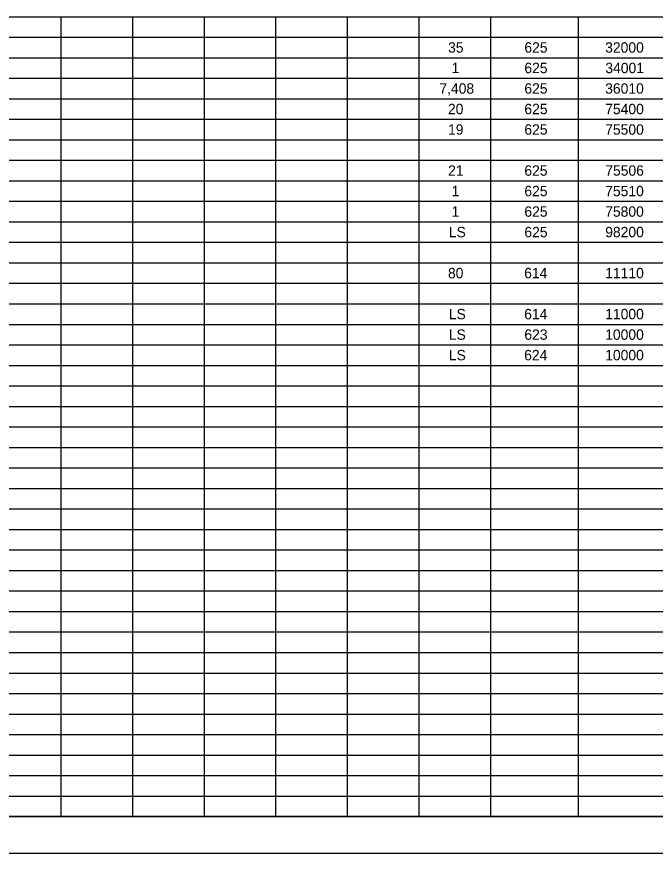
# Model space of a CAD drawing. Extents: x 0 to 34, y 0 to 22.
# Drawn here: x 8.71 to 17.43, y 0 to 11.42 of the extents above; entities that cross this region are included whole.
import ezdxf

# ---------------------------------------------------------------- set-up
doc = ezdxf.new("R2010")
doc.units = 0
for name, color, linetype in [('Default', 7, 'Continuous'), ('SH_Border', 7, 'Continuous'), ('SH_Cut_Line', 7, 'Continuous')]:
    doc.layers.add(name, color=color, linetype=linetype)

msp = doc.modelspace()

# ---------------------------------------------------------------- linework, layer by layer
at = {"layer": 'Default'}
for p, q in [((8.339, 11.42), (13.224, 11.42)), ((9.316, 11.42), (9.316, 10.3)), ((10.293, 11.42), (10.293, 10.3)), ((11.27, 11.42), (11.27, 10.3)), ((12.247, 11.42), (12.247, 10.3)), ((13.224, 11.42), (31.083, 11.42)), ((13.224, 11.42), (13.224, 10.3)), ((14.201, 11.42), (14.201, 10.3)), ((15.178, 11.42), (15.178, 10.3)), ((16.378, 11.42), (16.378, 10.3)), ((8.339, 11.14), (13.224, 11.14)), ((13.224, 11.14), (31.083, 11.14)), ((8.339, 10.86), (13.224, 10.86)), ((13.224, 10.86), (31.083, 10.86)), ((8.339, 10.58), (13.224, 10.58)), ((13.224, 10.58), (31.083, 10.58)), ((8.339, 10.3), (13.224, 10.3)), ((9.316, 10.3), (9.316, 10.02)), ((10.293, 10.3), (10.293, 10.02)), ((11.27, 10.3), (11.27, 10.02)), ((12.247, 10.3), (12.247, 10.02)), ((13.224, 10.3), (31.083, 10.3)), ((13.224, 10.3), (13.224, 10.02)), ((14.201, 10.3), (14.201, 10.02)), ((15.178, 10.3), (15.178, 10.02)), ((16.378, 10.3), (16.378, 10.02)), ((8.339, 10.02), (13.224, 10.02)), ((9.316, 10.02), (9.316, 9.741)), ((10.293, 10.02), (10.293, 9.741)), ((11.27, 10.02), (11.27, 9.741)), ((12.247, 10.02), (12.247, 9.741)), ((13.224, 10.02), (31.083, 10.02)), ((13.224, 10.02), (13.224, 9.741)), ((14.201, 10.02), (14.201, 9.741)), ((15.178, 10.02), (15.178, 9.741)), ((16.378, 10.02), (16.378, 9.741)), ((8.339, 9.741), (13.224, 9.741)), ((9.316, 9.741), (9.316, 8.901)), ((10.293, 9.741), (10.293, 8.901)), ((11.27, 9.741), (11.27, 8.901)), ((12.247, 9.741), (12.247, 8.901)), ((13.224, 9.741), (31.083, 9.741)), ((13.224, 9.741), (13.224, 8.901)), ((14.201, 9.741), (14.201, 8.901)), ((15.178, 9.741), (15.178, 8.901)), ((16.378, 9.741), (16.378, 8.901)), ((8.339, 9.461), (13.224, 9.461)), ((13.224, 9.461), (31.083, 9.461)), ((8.339, 9.181), (13.224, 9.181)), ((13.224, 9.181), (31.083, 9.181)), ((8.339, 8.901), (13.224, 8.901)), ((9.316, 8.901), (9.316, 8.341)), ((10.293, 8.901), (10.293, 8.341)), ((11.27, 8.901), (11.27, 8.341)), ((12.247, 8.901), (12.247, 8.341)), ((13.224, 8.901), (31.083, 8.901)), ((13.224, 8.901), (13.224, 8.341)), ((14.201, 8.901), (14.201, 8.341)), ((15.178, 8.901), (15.178, 8.341)), ((16.378, 8.901), (16.378, 8.341)), ((8.339, 8.621), (13.224, 8.621)), ((13.224, 8.621), (31.083, 8.621)), ((8.339, 8.341), (13.224, 8.341)), ((9.316, 8.341), (9.316, 7.501)), ((10.293, 8.341), (10.293, 7.501)), ((11.27, 8.341), (11.27, 7.501)), ((12.247, 8.341), (12.247, 7.501)), ((13.224, 8.341), (31.083, 8.341)), ((13.224, 8.341), (13.224, 7.501)), ((14.201, 8.341), (14.201, 7.501)), ((15.178, 8.341), (15.178, 7.501)), ((16.378, 8.341), (16.378, 7.501)), ((8.339, 8.061), (13.224, 8.061)), ((13.224, 8.061), (31.083, 8.061)), ((8.339, 7.781), (13.224, 7.781)), ((13.224, 7.781), (31.083, 7.781)), ((8.339, 7.501), (13.224, 7.501)), ((9.316, 7.501), (9.316, 6.941)), ((10.293, 7.501), (10.293, 6.941)), ((11.27, 7.501), (11.27, 6.941)), ((12.247, 7.501), (12.247, 6.941)), ((13.224, 7.501), (31.083, 7.501)), ((13.224, 7.501), (13.224, 6.941)), ((14.201, 7.501), (14.201, 6.941)), ((15.178, 7.501), (15.178, 6.941)), ((16.378, 7.501), (16.378, 6.941)), ((8.339, 7.221), (13.224, 7.221)), ((13.224, 7.221), (31.083, 7.221)), ((8.339, 6.941), (13.224, 6.941)), ((9.316, 6.941), (9.316, 6.101)), ((10.293, 6.941), (10.293, 6.101)), ((11.27, 6.941), (11.27, 6.101)), ((12.247, 6.941), (12.247, 6.101)), ((13.224, 6.941), (31.083, 6.941)), ((13.224, 6.941), (13.224, 6.101)), ((14.201, 6.941), (14.201, 6.101)), ((15.178, 6.941), (15.178, 6.101)), ((16.378, 6.941), (16.378, 6.101)), ((8.339, 6.661), (13.224, 6.661)), ((13.224, 6.661), (31.083, 6.661)), ((8.339, 6.381), (13.224, 6.381)), ((13.224, 6.381), (31.083, 6.381)), ((8.339, 6.101), (13.224, 6.101)), ((9.316, 6.101), (9.316, 4.981)), ((10.293, 6.101), (10.293, 4.981)), ((11.27, 6.101), (11.27, 4.981)), ((12.247, 6.101), (12.247, 4.981)), ((13.224, 6.101), (31.083, 6.101)), ((13.224, 6.101), (13.224, 4.981)), ((14.201, 6.101), (14.201, 4.981)), ((15.178, 6.101), (15.178, 4.981)), ((16.378, 6.101), (16.378, 4.981)), ((8.339, 5.821), (13.224, 5.821)), ((13.224, 5.821), (31.083, 5.821)), ((8.339, 5.541), (13.224, 5.541)), ((13.224, 5.541), (31.083, 5.541)), ((8.339, 5.261), (13.224, 5.261)), ((13.224, 5.261), (31.083, 5.261)), ((8.339, 4.981), (13.224, 4.981)), ((9.316, 4.981), (9.316, 4.701)), ((10.293, 4.981), (10.293, 4.701)), ((11.27, 4.981), (11.27, 4.701)), ((12.247, 4.981), (12.247, 4.701)), ((13.224, 4.981), (31.083, 4.981)), ((13.224, 4.981), (13.224, 4.701)), ((14.201, 4.981), (14.201, 4.701)), ((15.178, 4.981), (15.178, 4.701)), ((16.378, 4.981), (16.378, 4.701)), ((8.339, 4.701), (13.224, 4.701)), ((9.316, 4.701), (9.316, 3.581)), ((10.293, 4.701), (10.293, 3.581)), ((11.27, 4.701), (11.27, 3.581)), ((12.247, 4.701), (12.247, 3.581)), ((13.224, 4.701), (31.083, 4.701)), ((13.224, 4.701), (13.224, 3.581)), ((14.201, 4.701), (14.201, 3.581)), ((15.178, 4.701), (15.178, 3.581)), ((16.378, 4.701), (16.378, 3.581)), ((8.339, 4.421), (13.224, 4.421)), ((13.224, 4.421), (31.083, 4.421)), ((8.339, 4.141), (13.224, 4.141)), ((13.224, 4.141), (31.083, 4.141)), ((8.339, 3.861), (13.224, 3.861)), ((13.224, 3.861), (31.083, 3.861)), ((8.339, 3.581), (13.224, 3.581)), ((9.316, 3.581), (9.316, 3.301)), ((10.293, 3.581), (10.293, 3.301)), ((11.27, 3.581), (11.27, 3.301)), ((12.247, 3.581), (12.247, 3.301)), ((13.224, 3.581), (31.083, 3.581)), ((13.224, 3.581), (13.224, 3.301)), ((14.201, 3.581), (14.201, 3.301)), ((15.178, 3.581), (15.178, 3.301)), ((16.378, 3.581), (16.378, 3.301)), ((8.339, 3.301), (13.224, 3.301)), ((9.316, 3.301), (9.316, 2.181)), ((10.293, 3.301), (10.293, 2.181)), ((11.27, 3.301), (11.27, 2.181)), ((12.247, 3.301), (12.247, 2.181)), ((13.224, 3.301), (31.083, 3.301)), ((13.224, 3.301), (13.224, 2.181)), ((14.201, 3.301), (14.201, 2.181)), ((15.178, 3.301), (15.178, 2.181)), ((16.378, 3.301), (16.378, 2.181)), ((8.339, 3.021), (13.224, 3.021)), ((13.224, 3.021), (31.083, 3.021)), ((8.339, 2.741), (13.224, 2.741)), ((13.224, 2.741), (31.083, 2.741)), ((8.339, 2.461), (13.224, 2.461)), ((13.224, 2.461), (31.083, 2.461)), ((8.339, 2.181), (13.224, 2.181)), ((9.316, 2.181), (9.316, 1.901)), ((10.293, 2.181), (10.293, 1.901)), ((11.27, 2.181), (11.27, 1.901)), ((12.247, 2.181), (12.247, 1.901)), ((13.224, 2.181), (31.083, 2.181)), ((13.224, 2.181), (13.224, 1.901)), ((14.201, 2.181), (14.201, 1.901)), ((15.178, 2.181), (15.178, 1.901)), ((16.378, 2.181), (16.378, 1.901)), ((8.339, 1.901), (13.224, 1.901)), ((9.316, 1.901), (9.316, 0.781)), ((10.293, 1.901), (10.293, 0.781)), ((11.27, 1.901), (11.27, 0.781)), ((12.247, 1.901), (12.247, 0.781)), ((13.224, 1.901), (31.083, 1.901)), ((13.224, 1.901), (13.224, 0.781)), ((14.201, 1.901), (14.201, 0.781)), ((15.178, 1.901), (15.178, 0.781)), ((16.378, 1.901), (16.378, 0.781)), ((8.339, 1.621), (13.224, 1.621)), ((13.224, 1.621), (31.083, 1.621)), ((8.339, 1.341), (13.224, 1.341)), ((13.224, 1.341), (31.083, 1.341)), ((8.339, 1.061), (13.224, 1.061)), ((13.224, 1.061), (31.083, 1.061)), ((8.339, 0.781), (13.224, 0.781)), ((9.316, 0.781), (9.316, 0.501)), ((10.293, 0.781), (10.293, 0.501)), ((11.27, 0.781), (11.27, 0.501)), ((12.247, 0.781), (12.247, 0.501)), ((13.224, 0.781), (31.083, 0.781)), ((13.224, 0.781), (13.224, 0.501)), ((14.201, 0.781), (14.201, 0.501)), ((15.178, 0.781), (15.178, 0.501)), ((16.378, 0.781), (16.378, 0.501)), ((8.339, 0.501), (13.224, 0.501)), ((13.224, 0.501), (31.083, 0.501))]:
    msp.add_line(p, q, dxfattribs=at)
at = {"layer": 'SH_Border'}
msp.add_lwpolyline([(1.5, 21.5), (33.5, 21.5), (33.5, 0.5), (1.5, 0.5)], close=True, dxfattribs=at)
at = {"layer": 'SH_Cut_Line'}
msp.add_lwpolyline([(0, 0), (34, 0), (34, 22), (0, 22)], close=True, dxfattribs=at)

# ---------------------------------------------------------------- texts
at = {"layer": 'Default'}
for s, height, p in [('35', 0.1417, (14.601, 10.93)), ('625', 0.1417, (15.642, 10.93)), ('32000', 0.1417, (16.745, 10.93)), ('1', 0.142, (14.648, 10.65)), ('625', 0.1417, (15.642, 10.65)), ('34001', 0.1417, (16.747, 10.65)), ('7,408', 0.1417, (14.482, 10.37)), ('625', 0.1417, (15.642, 10.37)), ('36010', 0.1417, (16.745, 10.37)), ('20', 0.1417, (14.599, 10.09)), ('625', 0.1417, (15.642, 10.09)), ('75400', 0.1417, (16.745, 10.09)), ('19', 0.1417, (14.6, 9.81)), ('625', 0.1417, (15.642, 9.81)), ('75500', 0.1417, (16.745, 9.81)), ('21', 0.1417, (14.601, 9.25)), ('625', 0.1417, (15.642, 9.25)), ('75506', 0.1417, (16.746, 9.25)), ('1', 0.142, (14.648, 8.97)), ('625', 0.1417, (15.642, 8.97)), ('75510', 0.1417, (16.745, 8.97)), ('1', 0.142, (14.648, 8.69)), ('625', 0.1417, (15.642, 8.69)), ('75800', 0.1417, (16.745, 8.69)), ('LS', 0.1417, (14.611, 8.41)), ('625', 0.1417, (15.642, 8.41)), ('98200', 0.1417, (16.745, 8.41)), ('80', 0.1417, (14.599, 7.85)), ('614', 0.1417, (15.639, 7.85)), ('11110', 0.1417, (16.745, 7.85)), ('LS', 0.1417, (14.611, 7.29)), ('614', 0.1417, (15.639, 7.29)), ('11000', 0.1417, (16.745, 7.29)), ('LS', 0.1417, (14.611, 7.01)), ('623', 0.1417, (15.642, 7.01)), ('10000', 0.1417, (16.745, 7.01)), ('LS', 0.1417, (14.611, 6.73)), ('624', 0.1417, (15.639, 6.73)), ('10000', 0.1417, (16.745, 6.73))]:
    msp.add_text(s, height=height, dxfattribs=at).set_placement(p)

doc.saveas('drawing.dxf')
